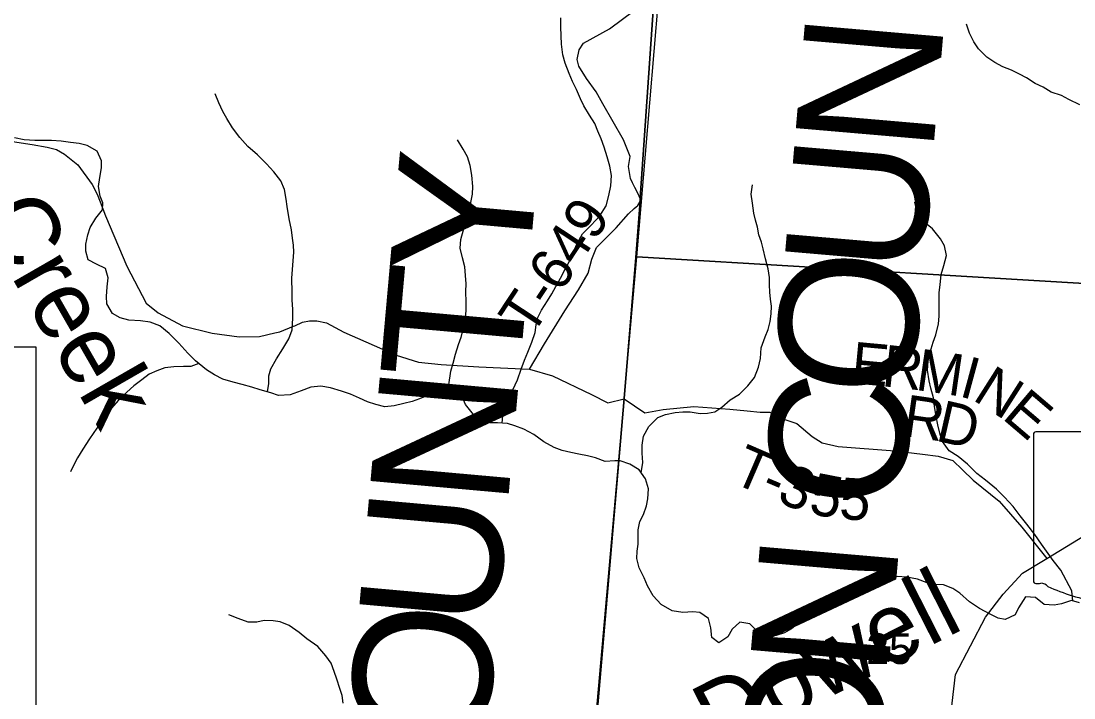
# Model space of a CAD drawing. Extents: x 0 to 40.8, y 0 to 22.
# Drawn here: x 6.756 to 8.193, y 18.425 to 19.348 of the extents above; entities that cross this region are included whole.
import ezdxf

# ---------------------------------------------------------------- set-up
doc = ezdxf.new("R2010")
doc.units = 0
for name, color, linetype in [('Default', 7, 'Continuous'), ('GM_X_County_Text', 7, 'Continuous'), ('GM_X_Minor_River', 7, 'Continuous'), ('GM_X_Minor_River_Text', 7, 'Continuous'), ('GM_X_Section', 7, 'Continuous'), ('GM_X_Section_Text', 7, 'Continuous'), ('GM_X_State_Route', 7, 'Continuous'), ('GM_X_State_Shield', 7, 'Continuous'), ('GM_X_Township_Road', 7, 'Continuous'), ('GM_X_Township_Road_Text', 7, 'Continuous'), ('SH_Cut_Line', 7, 'Continuous')]:
    doc.layers.add(name, color=color, linetype=linetype)

msp = doc.modelspace()

# ---------------------------------------------------------------- linework, layer by layer
at = {"layer": 'Default'}
msp.add_lwpolyline([(6.1785, 17.166), (6.9172, 17.1197), (7.4495, 17.0841), (7.4798, 17.5479), (7.4963, 17.9476), (7.5246, 18.2047), (7.5789, 18.8336), (7.595, 19.0259), (7.6007, 19.1025), (7.6007, 19.1071), (7.6192, 19.376), (7.7055, 20.511), (7.7204, 20.9), (3.6829, 20.9)], dxfattribs=at)
for points in [[(8.9, 16.9831), (8.9, 20.9), (7.7204, 20.9), (7.7055, 20.511), (7.6192, 19.376), (7.6007, 19.1071), (7.6007, 19.1025), (7.595, 19.0259), (7.5789, 18.8336), (7.5246, 18.2047), (7.4963, 17.9476), (7.4798, 17.5479), (7.4495, 17.0841), (7.54, 17.0745), (7.7144, 17.066), (7.7161, 17.0658)], [(5.1786, 18.9041), (6.7762, 18.9041), (6.7762, 17.7808), (5.1786, 17.7808)]]:
    msp.add_lwpolyline(points, close=True, dxfattribs=at)
at = {"layer": 'GM_X_Minor_River'}
for points in [[(7.4125, 18.8001), (7.4136, 18.816), (7.419, 18.8311), (7.427, 18.8455), (7.4332, 18.8591), (7.4386, 18.8735), (7.4428, 18.886), (7.4474, 18.8969), (7.4528, 18.9106), (7.4574, 18.9234), (7.459, 18.934), (7.461, 18.9439), (7.4663, 18.9541), (7.4743, 18.9666), (7.4801, 18.9764), (7.4855, 18.9862), (7.492, 18.9975), (7.4989, 19.0108), (7.5054, 19.0229), (7.5107, 19.0357), (7.5154, 19.046), (7.5222, 19.058), (7.5341, 19.0701), (7.5455, 19.0826), (7.5543, 19.0965), (7.5582, 19.1102), (7.5605, 19.1238), (7.5614, 19.1375), (7.5595, 19.1504), (7.5558, 19.1633), (7.5514, 19.1762), (7.5477, 19.1876), (7.5432, 19.1982), (7.5387, 19.2085), (7.5316, 19.2199), (7.5237, 19.2325), (7.5192, 19.242), (7.514, 19.2549), (7.5084, 19.2659), (7.5039, 19.2766), (7.4983, 19.2907), (7.4954, 19.3024), (7.4936, 19.3168), (7.4929, 19.3279), (7.4926, 19.3404), (7.4923, 19.3525)], [(8.2006, 19.234), (8.1858, 19.2412), (8.1756, 19.2469), (8.1613, 19.2515), (8.1507, 19.258), (8.1397, 19.263), (8.128, 19.271), (8.1182, 19.276), (8.1073, 19.2813), (8.0955, 19.2859), (8.0846, 19.2916), (8.0736, 19.2989), (8.0623, 19.3103), (8.0559, 19.3198), (8.0503, 19.3316), (8.0458, 19.3441)], [(7.0923, 18.8426), (7.0939, 18.8539), (7.094, 18.8645), (7.0967, 18.8743), (7.1044, 18.8876), (7.1131, 18.9012), (7.1216, 18.9148), (7.1258, 18.9272), (7.127, 18.9432), (7.1267, 18.9553), (7.1261, 18.9678), (7.1261, 18.9781), (7.1255, 18.9978), (7.1263, 19.0095), (7.1275, 19.0213), (7.128, 19.033), (7.1277, 19.0425), (7.1266, 19.0524), (7.1251, 19.0638), (7.1218, 19.0786), (7.1193, 19.0953), (7.1178, 19.1055), (7.1153, 19.1188), (7.1104, 19.1302), (7.101, 19.1428), (7.0909, 19.1535), (7.0784, 19.166), (7.0656, 19.1771), (7.0547, 19.1897), (7.0446, 19.2027), (7.0367, 19.2156), (7.0315, 19.2251), (7.0259, 19.2369), (7.0207, 19.2491)], [(7.5662, 18.7487), (7.5529, 18.7477), (7.5396, 18.7527), (7.5291, 18.7554), (7.517, 18.7577), (7.506, 18.7601), (7.4943, 18.7628), (7.4833, 18.767), (7.4694, 18.7747), (7.4558, 18.7846), (7.4418, 18.7919), (7.4298, 18.7965), (7.4196, 18.7996), (7.4063, 18.8005), (7.3965, 18.8005), (7.3836, 18.804), (7.3734, 18.812), (7.3622, 18.8254), (7.3569, 18.8383), (7.3502, 18.8512), (7.3389, 18.8524), (7.3271, 18.8457), (7.3138, 18.8393), (7.2997, 18.8333), (7.2895, 18.8296), (7.2785, 18.827), (7.2649, 18.8237), (7.2524, 18.8222), (7.2399, 18.8253), (7.2289, 18.8292), (7.2176, 18.8342), (7.2055, 18.8396), (7.1934, 18.8438), (7.1783, 18.8481), (7.1651, 18.8504), (7.1514, 18.849), (7.1382, 18.8441), (7.123, 18.8385), (7.1074, 18.8375), (7.0969, 18.8413), (7.0821, 18.8456), (7.0708, 18.8491), (7.0579, 18.8526), (7.0455, 18.8557), (7.0311, 18.8599), (7.0198, 18.8657), (7.0089, 18.8729), (6.9942, 18.8852), (6.9836, 18.8955), (6.9712, 18.9092), (6.958, 18.9221), (6.9452, 18.9328), (6.9324, 18.9378), (6.9192, 18.9394), (6.9033, 18.9403), (6.8912, 18.9434), (6.881, 18.9495), (6.8731, 18.9625), (6.8728, 18.9727), (6.8736, 18.986), (6.8749, 18.9981), (6.8711, 19.011), (6.8591, 19.0168), (6.8474, 19.0229), (6.8444, 19.0347), (6.8445, 19.0442), (6.8472, 19.057), (6.8503, 19.0669), (6.8579, 19.0793), (6.8671, 19.0907), (6.8675, 19.1002), (6.8638, 19.1097), (6.8616, 19.1226), (6.8636, 19.1351), (6.8656, 19.1479), (6.8656, 19.1578), (6.86, 19.1707), (6.8464, 19.1784), (6.8355, 19.1811), (6.8234, 19.1827), (6.8109, 19.1847), (6.7977, 19.1855), (6.7746, 19.1856), (6.7602, 19.1861), (6.7469, 19.1892)], [(7.3396, 18.8524), (7.3424, 18.871), (7.3455, 18.882), (7.3486, 18.8941), (7.3528, 18.9073), (7.3563, 18.9172), (7.3602, 18.9312), (7.3625, 18.9414), (7.3633, 18.9547), (7.3634, 18.9649), (7.3631, 18.9793), (7.3632, 18.99), (7.3625, 19.0013), (7.3614, 19.0131), (7.3585, 19.0256), (7.3552, 19.0385), (7.356, 19.0503), (7.3599, 19.0635), (7.363, 19.0745), (7.3657, 19.0859), (7.3692, 19.0988), (7.3719, 19.112), (7.3723, 19.1226), (7.3709, 19.1382), (7.3687, 19.1511), (7.365, 19.1633), (7.3594, 19.1735), (7.3515, 19.1861)], [(7.602, 18.7324), (7.6046, 18.7465), (7.6035, 18.759), (7.6036, 18.77), (7.6055, 18.7825), (7.6127, 18.7954), (7.6249, 18.8079), (7.6355, 18.8116), (7.6484, 18.8146), (7.659, 18.8153), (7.6688, 18.8153), (7.6824, 18.8134), (7.6927, 18.8137), (7.7025, 18.8156), (7.712, 18.8216), (7.7234, 18.8318), (7.7363, 18.8397), (7.7477, 18.8507), (7.7568, 18.8624), (7.7621, 18.8764), (7.7648, 18.8882), (7.766, 18.9026), (7.7714, 18.9177), (7.7752, 18.9275), (7.7783, 18.9385), (7.7794, 18.9491), (7.7799, 18.9594), (7.7784, 18.9692), (7.7777, 18.9787), (7.7773, 18.9886), (7.777, 18.9984), (7.7755, 19.0106), (7.7718, 19.0239), (7.7684, 19.0375), (7.7662, 19.047), (7.7628, 19.0569), (7.7609, 19.0671), (7.7583, 19.0766), (7.7557, 19.0865), (7.7539, 19.1001), (7.7524, 19.1123), (7.7539, 19.1248)], [(8.1912, 18.5574), (8.1895, 18.5716), (8.1745, 18.5997), (8.1643, 18.6127), (8.1553, 18.6256), (8.1481, 18.6351), (8.1391, 18.648), (8.1285, 18.6621), (8.1191, 18.6738), (8.1097, 18.6864), (8.098, 18.6989), (8.0867, 18.71), (8.072, 18.7222), (8.0603, 18.7313), (8.0474, 18.7439), (8.0346, 18.7545), (8.0225, 18.7625), (8.0131, 18.7751), (8.0101, 18.7846), (8.0071, 18.7978), (8.0045, 18.8096), (8.0023, 18.8229), (8.0008, 18.8346), (7.9971, 18.8479), (7.9949, 18.8578), (7.993, 18.8722), (7.9938, 18.8847), (7.9965, 18.8968), (8.0007, 18.9105), (8.0042, 18.9203), (8.0076, 18.9355), (8.0088, 18.9461), (8.0088, 18.9571), (8.0085, 18.9677), (8.0089, 18.9783), (8.0101, 18.9885), (8.0113, 19.0026), (8.0151, 19.0151), (8.0189, 19.0287), (8.0159, 19.0416), (8.0103, 19.0515), (7.9994, 19.0648), (7.9873, 19.0751), (7.9786, 19.088), (7.9753, 19.1013)], [(6.9988, 18.8813), (6.9877, 18.8772), (6.9778, 18.8773), (6.9646, 18.877), (6.9521, 18.8755), (6.9415, 18.8714), (6.9308, 18.8666), (6.9209, 18.859), (6.9099, 18.8508), (6.9004, 18.8421), (6.889, 18.8312), (6.879, 18.8198), (6.8703, 18.8066), (6.8596, 18.7934), (6.8496, 18.7787), (6.8401, 18.7647), (6.8332, 18.7526), (6.8278, 18.7424), (6.8235, 18.7338)], [(7.8962, 18.5802), (7.8864, 18.5757), (7.8761, 18.57), (7.8655, 18.5629), (7.8556, 18.5557), (7.8462, 18.5493), (7.8325, 18.5395), (7.8207, 18.5308), (7.8071, 18.5198), (7.7976, 18.5142), (7.7862, 18.5104), (7.7764, 18.5093), (7.7631, 18.5139), (7.7503, 18.5265), (7.7367, 18.5288), (7.7261, 18.519), (7.7203, 18.5088), (7.7082, 18.5005), (7.6984, 18.5077), (7.6973, 18.521), (7.6939, 18.5339), (7.6822, 18.5419), (7.6724, 18.5427), (7.6588, 18.542), (7.6444, 18.5443), (7.6293, 18.5527), (7.6184, 18.5645), (7.6108, 18.5781), (7.6063, 18.5892), (7.5996, 18.6028), (7.5962, 18.6157), (7.5966, 18.6256), (7.5982, 18.6351), (7.5982, 18.6544), (7.6005, 18.6658), (7.6055, 18.6756), (7.6093, 18.6873), (7.6113, 18.6968), (7.6121, 18.7105), (7.6079, 18.7241), (7.5993, 18.7363), (7.5868, 18.7443), (7.5736, 18.7485), (7.5662, 18.7487)], [(8.2001, 18.5549), (8.1891, 18.558), (8.1755, 18.5535), (8.1656, 18.552), (8.152, 18.5528), (8.1403, 18.5623), (8.1267, 18.5631), (8.1171, 18.5484), (8.1122, 18.5385), (8.0989, 18.5321), (8.0891, 18.534), (8.0781, 18.5394), (8.0638, 18.5474), (8.0502, 18.5565), (8.037, 18.568), (8.0272, 18.5744), (8.0147, 18.5794), (8.0026, 18.5802), (7.9924, 18.5825), (7.9791, 18.5875), (7.9644, 18.5902), (7.9515, 18.591), (7.9402, 18.5895), (7.9303, 18.5877), (7.9197, 18.5862), (7.9083, 18.5843), (7.8962, 18.5802)], [(7.1957, 18.4183), (7.1942, 18.4286), (7.1909, 18.4384), (7.1868, 18.451), (7.1831, 18.4616), (7.179, 18.4726), (7.1719, 18.4829), (7.161, 18.4955), (7.1459, 18.5058), (7.1357, 18.5146), (7.1218, 18.5242), (7.1097, 18.5292), (7.0999, 18.5307), (7.0877, 18.5308), (7.0775, 18.5286), (7.0658, 18.5287), (7.0522, 18.5337), (7.0397, 18.5387)]]:
    msp.add_lwpolyline(points, dxfattribs=at)
at = {"layer": 'GM_X_Section'}
for points in [[(7.6848, 20.077), (8.6564, 20.0646), (8.5831, 19.0989), (8.5731, 18.9686), (7.596, 19.0268)], [(7.596, 19.0268), (8.5731, 18.9686), (8.5049, 18.0532), (8.5005, 17.9979), (7.5081, 18.0324)]]:
    msp.add_lwpolyline(points, close=True, dxfattribs=at)
at = {"layer": 'GM_X_State_Route'}
msp.add_lwpolyline([(7.48, 17.5474), (7.9684, 17.5164), (7.9928, 17.859), (8.0065, 18.059), (8.0171, 18.336), (8.0308, 18.4575), (8.0718, 18.5354), (8.0962, 18.5668), (8.1225, 18.5953), (8.1555, 18.6155), (8.2175, 18.6534), (8.273, 18.6963), (8.3555, 18.766)], dxfattribs=at)
at = {"layer": 'GM_X_State_Shield'}
for p, q in [((8.1375, 18.7848), (8.1375, 18.5847)), ((8.2372, 18.7883), (8.1407, 18.7883))]:
    msp.add_line(p, q, dxfattribs=at)
for centre, major_axis, start_param, end_param in [((8.1413, 18.7853), (0.00382, 0), 1.712693, 3.28349), ((8.1413, 18.5843), (0.00385, 0), 3.00124, 4.508301), ((8.1419, 18.6048), (0.0294, 0), 4.665946, 4.897461), ((8.1479, 18.5732), (0.0106, 0), 0.519207, 1.627899), ((8.2817, 18.753), (0.2524, 0), 4.195997, 4.488961)]:
    msp.add_ellipse(centre, major_axis=major_axis, ratio=0.8, start_param=start_param, end_param=end_param, dxfattribs=at)
at = {"layer": 'GM_X_Township_Road'}
for points in [[(7.5969, 19.1144), (7.5933, 19.1214), (7.5905, 19.1275), (7.5876, 19.1336), (7.585, 19.1499), (7.5873, 19.1636), (7.5782, 19.1865), (7.5497, 19.2356), (7.5406, 19.2516), (7.5277, 19.2699), (7.5171, 19.2867), (7.5148, 19.2958), (7.5175, 19.3091), (7.5232, 19.3179), (7.559, 19.3375), (7.5926, 19.3626), (7.6194, 19.3755)], [(6.7444, 19.1842), (6.771, 19.1799), (6.7916, 19.1761), (6.8045, 19.173), (6.8152, 19.1669), (6.8334, 19.1524), (6.8531, 19.1253), (6.86, 19.112), (6.8638, 19.1017), (6.8713, 19.0827), (6.9002, 19.0141), (6.9267, 18.9635), (6.9431, 18.9505), (6.9762, 18.9325), (7.0169, 18.9225), (7.0534, 18.9175), (7.0812, 18.9182), (7.1025, 18.923)], [(7.5953, 19.0948), (7.5975, 19.0967), (7.6009, 19.102), (7.6009, 19.1065), (7.5995, 19.1093), (7.5969, 19.1144)], [(7.4499, 18.8734), (7.4701, 18.9083), (7.4979, 18.9532), (7.5166, 18.982), (7.5296, 19.0044), (7.5346, 19.0238), (7.5411, 19.0394), (7.5678, 19.0663), (7.5849, 19.0853), (7.5925, 19.0925), (7.5953, 19.0948)], [(7.1025, 18.923), (7.1093, 18.9246), (7.1278, 18.9322), (7.1295, 18.9329), (7.1402, 18.9378), (7.1497, 18.9397), (7.1596, 18.9396), (7.1729, 18.9369), (7.1965, 18.9239), (7.2676, 18.8929), (7.2984, 18.8833), (7.3292, 18.8802), (7.3806, 18.877), (7.4499, 18.8734), (7.4811, 18.8646), (7.5343, 18.8393), (7.5564, 18.8275), (7.5791, 18.8331)], [(7.5791, 18.8331), (7.6072, 18.814), (7.6323, 18.8186), (7.674, 18.8229), (7.7233, 18.8189), (7.7468, 18.8166), (7.7646, 18.8152), (7.7775, 18.8148), (7.7915, 18.8073), (7.8147, 18.7997), (7.8356, 18.782), (7.8492, 18.7733), (7.8709, 18.768), (7.9482, 18.7625), (7.9858, 18.7577), (8.0074, 18.7551), (8.0275, 18.749), (8.0404, 18.7366), (8.0549, 18.7222), (8.0906, 18.6938), (8.1217, 18.6582), (8.1555, 18.6155)]]:
    msp.add_lwpolyline(points, dxfattribs=at)
at = {"layer": 'SH_Cut_Line'}
for points in [[(7.7204, 20.9), (2.1, 20.9), (2.1, 17.4153), (2.4594, 17.3966), (2.8463, 17.3693), (2.8484, 17.3691), (3.1244, 17.3534), (3.4481, 17.3334), (4.5348, 17.2687), (4.8294, 17.2493), (5.3407, 17.2146), (5.6278, 17.197), (6.1785, 17.166), (6.9172, 17.1197), (7.4495, 17.0841), (7.4798, 17.5479), (7.4963, 17.9476), (7.5246, 18.2047), (7.5789, 18.8336), (7.595, 19.0259), (7.6007, 19.1025), (7.6007, 19.1071), (7.6192, 19.376), (7.7055, 20.511)], [(8.9, 16.9831), (8.9, 20.9), (7.7204, 20.9), (7.7055, 20.511), (7.6192, 19.376), (7.6007, 19.1071), (7.6007, 19.1025), (7.595, 19.0259), (7.5789, 18.8336), (7.5246, 18.2047), (7.4963, 17.9476), (7.4798, 17.5479), (7.4495, 17.0841), (7.54, 17.0745), (7.7144, 17.066), (7.7161, 17.0658)]]:
    msp.add_lwpolyline(points, close=True, dxfattribs=at)

# ---------------------------------------------------------------- texts
at = {"layer": 'GM_X_County_Text'}
for s, rotation, p in [('N', 85.0779, (8.0001, 19.1653)), ('Y', 84.8886, (7.4472, 18.9916)), ('U', 85.0787, (7.9857, 18.9985)), ('O', 85.0789, (7.9713, 18.8316)), ('T', 84.889, (7.4346, 18.8505)), ('N', 84.8903, (7.4196, 18.6836)), ('C', 85.0787, (7.9581, 18.678)), ('U', 84.8886, (7.4047, 18.5168)), ('N', 85.0811, (7.9388, 18.4538)), ('O', 84.8889, (7.3898, 18.35)), ('O', 85.1215, (7.9246, 18.287))]:
    msp.add_text(s, height=0.1894, rotation=rotation, dxfattribs=at).set_placement(p)
at = {"layer": 'GM_X_Minor_River_Text'}
for s, rotation, p in [('Creek', 299.8895, (6.6962, 19.0802)), ('McDowell', 27.005, (7.5557, 18.2713))]:
    msp.add_text(s, height=0.0947, rotation=rotation, dxfattribs=at).set_placement(p)
at = {"layer": 'GM_X_Section_Text'}
msp.add_text('25', height=0.04186, rotation=0, dxfattribs=at).set_placement((7.9092, 18.4716))
at = {"layer": 'GM_X_Township_Road_Text'}
for s, height, rotation, p in [('T-649', 0.05682, 56.5258, (7.4523, 18.9163)), ('E', 0.0568, 354.7342, (7.887, 18.8546)), ('R', 0.0568, 353.6486, (7.9291, 18.8507)), ('M', 0.0568, 351.692, (7.975, 18.8456)), ('I', 0.0568, 344.7955, (8.0342, 18.8371)), ('N', 0.0568, 327.5255, (8.0526, 18.8328)), ('R', 0.0568, 351.8743, (7.9573, 18.7829)), ('E', 0.0568, 319.587, (8.0931, 18.8072)), ('D', 0.0568, 347.0938, (8.0023, 18.7765)), ('T', 0.0568, 336.6298, (7.7234, 18.7202)), ('3', 0.0568, 338.109, (7.7853, 18.6936)), ('-', 0.0568, 336.877, (7.7626, 18.7033)), ('5', 0.0568, 348.9768, (7.8291, 18.6772)), ('5', 0.0568, 356.372, (7.8713, 18.6695))]:
    msp.add_text(s, height=height, rotation=rotation, dxfattribs=at).set_placement(p)

doc.saveas('drawing.dxf')
